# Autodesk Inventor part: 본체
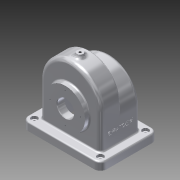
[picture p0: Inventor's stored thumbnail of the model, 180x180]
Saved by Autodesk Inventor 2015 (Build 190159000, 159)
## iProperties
Created: 2017-11
Part Number: 본체
Material: 알루미늄 6061
Document SubType Name: Modeling
Designer: SCD-A12
Density: 2.7 g/cm^3
Appearance: 알루미늄 - 평지
Mass: 1076.64 g
Surface Area: 1181.67 cm^2
Volume: 398.755 cm^3
Author: SCD-A12
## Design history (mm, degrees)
sketch "스케치6"
  geometry: L1 (-58, 0)-(-58, -80); L2 (-58, -80)-(58, -80); L3 (58, -80)-(58, 0); A1 r 58 centre (0, 0) between (-58, 0) and (58, 0); 1 further point
  constraints: 6 end point, 2 point on circle, 2 tangent, 1 centre point, 1 coincident, 1 perpendicular, 1 vertical
  dimensions: "d28" = 58 radius of A1; "d29" = 80 distance of L1.start L1.end; "d30" = 116 distance between parallel lines of L1 L3 (derived)
extrude "돌출5" new body sketch "스케치6" distance "d31" = 38; taper "d32" = 0 deg
sketch "스케치7"
  geometry: L1 (-58, -80)-(58, -80) reference; L2 (0, -80)-(0, -23); L3 (-58, -23)-(-58, -80); L4 (-58, -80)-(58, -80); L5 (58, -80)-(58, 0) reference; L6 (58, -23)-(58, -80); A1 r 58 centre (0, -23) between (10.724, -80) and (-10.724, -80); 1 further point
  constraints: 8 end point, 4 point on circle, 3 point on line, 2 collinear, 1 centre point, 1 coincident, 1 midpoint, 1 tangent, 1 vertical
  dimensions: "d33" = 57 distance of L2.start L2.end; "d34" = 58 radius of A1
extrude "돌출6" join sketch "스케치7" distance "d35" = 38; taper "d36" = 0 deg
sketch "스케치8"
  geometry: 1 further point
feature "쉘2" dims "d37" = 5
sketch "스케치9"
  geometry: L1 (0, 0)-(-80, 0) reference; L2 (58, 0)-(0, 0) reference; L3 (-23, -76)-(35, -76) reference; L4 (-80, -76)-(-23, -76) reference; L5 (-80, -71)-(-80, -5) reference; L6 (-80, -38)-(-15, -38); L7 (-15, 27.292)-(-15, -103.292); L8 (22.5, 0)-(1, 0); L9 (1, 0)-(1, 9); L10 (1, 9)-(22.5, 9); L11 (22.5, 9)-(22.5, 0); L12 (16, -76)-(1, -76); L13 (1, -76)-(1, -86); L14 (1, -86)-(16, -86); L15 (16, -86)-(16, -76)
  constraints: 20 end point, 4 parallel, 3 horizontal, 2 midpoint, 2 perpendicular, 2 point on line, 1 vertical
  dimensions: "d38" = 65 distance of L6.end L6.start; "d39" = 75 diameter of L11 L7; "d40" = 32 diameter of L9 L7; "d41" = 32 diameter of L13 L7; "d42" = 62 diameter of L15 L7; "d43" = 9 distance between parallel lines of L2 L10; "d44" = 86 distance between parallel lines of L14 L2
revolve "회전1" sketch "스케치9" stored, may be unused: angle "d45" = 90 deg
sketch "스케치10"
  geometry: 1 further point
sketch "스케치11"
  geometry: C1 r 16 at (0, 0); 1 further point
  constraints: 1 centre point
  dimensions: "d46" = 32 diameter of C1
extrude "돌출7" cut sketch "스케치11" distance "d47" = 114; taper "d48" = 0 deg
sketch "스케치12"
  geometry: L1 (116, -38)-(0, -38); L2 (0, 0)-(0, -76) reference; L3 (42, -86)-(74, -86) reference; L4 (58, -86)-(58, 9); L5 (20.5, 9)-(95.5, 9) reference; L6 (5, -5)-(111, -5) reference; L7 (58, -5)-(133, -5); L8 (133, -5)-(133, 17); L9 (133, 17)-(58, 17); L10 (58, 17)-(58, -5); L11 (111, -5)-(111, -71) reference; L12 (133, 17)-(111, 17); L13 (111, 17)-(111, -38); L14 (111, -38)-(133, -38); L15 (133, -38)-(133, 17); 1 further point
  constraints: 20 end point, 5 midpoint, 4 parallel, 2 horizontal, 2 perpendicular
  dimensions: "d49" = 150 diameter of L8 L4; "d50" = 110 diameter of L9 L1
extrude "돌출8" join sketch "스케치12" distance "d51" = 15; taper "d52" = 0 deg
node "작업 평면1"
sketch "스케치13"
  geometry: L1 (-150, 0)-(-150, 110) reference; L2 (0, 110)-(0, 0) reference; L3 (0, 110)-(-150, 110) reference; L4 (-17, 93)-(-133, 93) reference; L5 (-133, 55)-(-17, 55) reference; L6 (-75, 93)-(-75, 74); C1 r 6 at (-75, 74); 1 further point
  constraints: 2 coincident, 2 end point, 1 centre point, 1 vertical
  dimensions: "d54" = 19 distance of L6.start L6.end; "d55" = 12 diameter of C1
extrude "돌출9" join sketch "스케치13" stored distance "d56" = 15; taper "d57" = 0 deg
hole "구멍1" diameter "d60" = 4.459; stored, may be unused: countersink angle "d64" = 90 deg, drill point angle "d66" = 118 deg; dims "d58" = 10, "d59" = 10, "d61" = 10, "d62" = 4, "d63" = 2, "d65" = 31.02123
fillet "모깎기1" dims "d67" = 12
hole "구멍2" diameter "d70" = 5; stored, may be unused: countersink angle "d74" = 90 deg, drill point angle "d76" = 118 deg; dims "d68" = 10, "d69" = 10, "d71" = 10, "d72" = 12, "d73" = 5, "d75" = 31.02123
hole "구멍3" diameter "d79" = 5; stored, may be unused: countersink angle "d83" = 90 deg, drill point angle "d85" = 118 deg; dims "d77" = 10, "d78" = 10, "d80" = 10, "d81" = 12, "d82" = 5, "d84" = 31.02123
sketch "스케치14" dims "d86" = 58
  geometry: 3 further points
  constraints: 1 vertical alignment, 2 other
hole "구멍4" sketch "스케치14" at (0, 29) diameter "d87" = 2.459; stored, may be unused: countersink angle "d91" = 90 deg, drill point angle "d93" = 118 deg; dims "d88" = 6, "d89" = 4, "d90" = 2, "d92" = 8
sketch "스케치15" dims "d97" = 52
  geometry: 3 further points
  constraints: 1 vertical alignment, 2 other
hole "구멍5" sketch "스케치15" at (0, 26) diameter "d98" = 2.459; stored, may be unused: countersink angle "d102" = 90 deg, drill point angle "d104" = 118 deg; dims "d99" = 6, "d100" = 4, "d101" = 2, "d103" = 8
fillet "모깎기2" dims "d108" = 3
fillet "모깎기3" dims "d109" = 3, "d110" = 8
chamfer "모따기1" distance "d111" = 1; stored, may be unused: second distance "d112" = 2, angle "d113" = 45 deg
node "작업 평면2"
sketch "스케치16"
  geometry: L1 (0, 0)-(-62, 0) reference; L2 (-80, -81)-(-80, 5) reference; L3 (-80, -68)-(-80, -8) reference; L4 (-80, -38)-(-40, -38); L5 (-40, -38)-(-40, 0); 2 further points
  constraints: 4 end point, 2 coincident, 1 horizontal, 1 midpoint, 1 point on line, 1 other
  dimensions: "d116" = 40 distance of L4.start L4.end; "d117" = 38 distance of L4.end L5.end
feature "엠보싱1" sketch "스케치16" dims "d118" = 0.5, "d119" = 0
node "솔리드3"
mirror "대칭1"
mirror "대칭2"
mirror "대칭3"
pattern_circular "원형 패턴1" dims angle "d95" = 360 deg
pattern_circular "원형 패턴2" dims angle "d106" = 360 deg
other parameters: "d53" = -144, "d114" = 180.25
